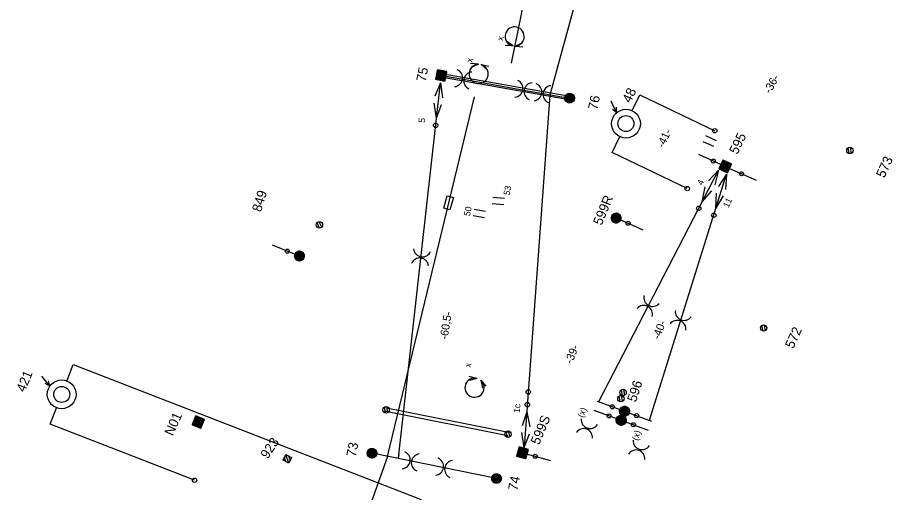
# Model space of a CAD drawing. Extents: x -595867 to -593796, y -1159595 to -1157495.
# Drawn here: x -594756.8 to -594620.1, y -1157925.4 to -1157851.2 of the extents above; entities that cross this region are included whole.
import ezdxf

# ---------------------------------------------------------------- set-up
doc = ezdxf.new("R2010")
doc.units = 0
for name, color, linetype in [('BVK_kanalizace_destova_nova', 7, 'Continuous'), ('BVK_kanalizace_jednotna_nova', 7, 'Continuous'), ('CD Telematika_novy', 7, 'Continuous')]:
    doc.layers.add(name, color=color, linetype=linetype)

# ---------------------------------------------------------------- blocks, each defined once
blk = doc.blocks.new('st_1t')
for points in [[(-0.0074, 0.0007), (0.0028, 0.0069), (0.0036, 0.0066), (-0.0075, -0.0002)], [(-0.0075, -0.0002), (0.0036, 0.0066), (0.0044, 0.006), (-0.0074, -0.001)], [(-0.0073, 0.0016), (0.0019, 0.0072), (0.0028, 0.0069), (-0.0074, 0.0007)], [(-0.0074, -0.001), (0.0044, 0.006), (0.0052, 0.0054), (-0.0072, -0.0019)], [(-0.0071, 0.0022), (0.0006, 0.0074), (0.0019, 0.0072), (-0.0073, 0.0016)], [(-0.0072, -0.0019), (0.0052, 0.0054), (0.0059, 0.0046), (-0.0069, -0.003)], [(-0.0069, 0.0029), (-0.0001, 0.0075), (0.0006, 0.0074), (-0.0071, 0.0022)], [(-0.0067, 0.0033), (-0.0015, 0.0073), (-0.0001, 0.0075), (-0.0069, 0.0029)], [(-0.0069, -0.003), (0.0059, 0.0046), (0.0067, 0.0034), (-0.0064, -0.0039)], [(-0.0063, 0.004), (-0.0022, 0.0071), (-0.0015, 0.0073), (-0.0067, 0.0033)], [(-0.0064, -0.0039), (0.0067, 0.0034), (0.0071, 0.0022), (-0.0057, -0.0049)], [(-0.0058, 0.0047), (-0.0032, 0.0068), (-0.0022, 0.0071), (-0.0063, 0.004)], [(-0.0053, 0.0053), (-0.0041, 0.0062), (-0.0032, 0.0068), (-0.0058, 0.0047)], [(-0.0057, -0.0049), (0.0071, 0.0022), (0.0074, 0.0011), (-0.0049, -0.0056)], [(-0.0049, -0.0056), (0.0074, 0.0011), (0.0075, -0.0004), (-0.004, -0.0063)], [(-0.004, -0.0063), (0.0075, -0.0004), (0.0073, -0.0017), (-0.0032, -0.0068)], [(-0.0032, -0.0068), (0.0073, -0.0017), (0.007, -0.0027), (-0.0021, -0.0072)], [(-0.0021, -0.0072), (0.007, -0.0027), (0.0065, -0.0037), (-0.0011, -0.0074)], [(-0.0011, -0.0074), (0.0065, -0.0037), (0.0059, -0.0046), (-0.0005, -0.0075)], [(-0.0005, -0.0075), (0.0059, -0.0046), (0.0054, -0.0052), (0.0004, -0.0075)], [(0.0004, -0.0075), (0.0054, -0.0052), (0.0045, -0.006), (0.0014, -0.0074)], [(0.0014, -0.0074), (0.0045, -0.006), (0.0038, -0.0064), (0.0025, -0.007)], [(0.0025, -0.007), (0.0038, -0.0064), (0.0029, -0.0069), (0.0029, -0.0069)]]:
    blk.add_lwpolyline(points, close=True)
blk.add_circle((0, 0), 0.0075)
blk = doc.blocks.new('st_tecka')
blk.add_circle((0, 0), 0.00314)
blk = doc.blocks.new('st1k_1t')
blk.add_line((0, 0), (0.0453, 0))
blk.add_blockref('st_1t', (0, 0))
at = {"rotation": 90}
blk.add_blockref('st_tecka', (0.0205, 0), dxfattribs=at)
blk = doc.blocks.new('st_bp')
for p, q in [((0.0075, 0.0075), (-0.0075, 0.0075)), ((-0.0075, 0.0075), (-0.0075, -0.0075)), ((-0.0075, -0.0075), (0.0075, 0.0075)), ((-0.0075, -0.0071), (0.0071, 0.0075)), ((-0.0075, -0.0067), (0.0067, 0.0075)), ((-0.0075, -0.0062), (0.0062, 0.0075)), ((-0.0075, -0.0058), (0.0058, 0.0075)), ((-0.0075, -0.0054), (0.0054, 0.0075)), ((-0.0075, -0.005), (0.005, 0.0075)), ((-0.0075, -0.0045), (0.0045, 0.0075)), ((-0.0075, -0.0041), (0.0041, 0.0075)), ((-0.0075, -0.0037), (0.0037, 0.0075)), ((-0.0075, -0.0033), (0.0033, 0.0075)), ((-0.0075, -0.0028), (0.0028, 0.0075)), ((-0.0075, -0.0024), (0.0024, 0.0075)), ((-0.0075, -0.002), (0.002, 0.0075)), ((-0.0075, -0.0016), (0.0016, 0.0075)), ((-0.0075, -0.0011), (0.0011, 0.0075)), ((-0.0075, -0.0007), (0.0007, 0.0075)), ((-0.0075, -0.0003), (0.0003, 0.0075)), ((-0.0075, 0.0001), (-0.0001, 0.0075)), ((-0.0075, 0.0006), (-0.0006, 0.0075)), ((-0.0075, 0.001), (-0.001, 0.0075)), ((-0.0075, 0.0014), (-0.0014, 0.0075)), ((-0.0075, 0.0018), (-0.0018, 0.0075)), ((-0.0075, 0.0023), (-0.0023, 0.0075)), ((-0.0075, 0.0027), (-0.0027, 0.0075)), ((-0.0075, 0.0031), (-0.0031, 0.0075)), ((-0.0075, 0.0035), (-0.0035, 0.0075)), ((-0.0075, 0.004), (-0.004, 0.0075)), ((-0.0075, 0.0044), (-0.0044, 0.0075)), ((-0.0075, 0.0048), (-0.0048, 0.0075)), ((-0.0075, 0.0052), (-0.0052, 0.0075)), ((-0.0075, 0.0057), (-0.0057, 0.0075)), ((-0.0075, 0.0061), (-0.0061, 0.0075)), ((-0.0075, 0.0065), (-0.0065, 0.0075)), ((-0.0075, 0.0069), (-0.0069, 0.0075)), ((-0.0075, 0.0073), (-0.0073, 0.0075)), ((-0.0071, -0.0075), (0.0075, 0.0071)), ((-0.0067, -0.0075), (0.0075, 0.0067)), ((-0.0062, -0.0075), (0.0075, 0.0062)), ((-0.0058, -0.0075), (0.0075, 0.0058)), ((-0.0054, -0.0075), (0.0075, 0.0054)), ((-0.005, -0.0075), (0.0075, 0.005)), ((-0.0045, -0.0075), (0.0075, 0.0045)), ((-0.0041, -0.0075), (0.0075, 0.0041)), ((-0.0037, -0.0075), (0.0075, 0.0037)), ((-0.0033, -0.0075), (0.0075, 0.0033)), ((-0.0028, -0.0075), (0.0075, 0.0028)), ((-0.0024, -0.0075), (0.0075, 0.0024)), ((-0.002, -0.0075), (0.0075, 0.002)), ((-0.0016, -0.0075), (0.0075, 0.0016)), ((-0.0011, -0.0075), (0.0075, 0.0011)), ((-0.0007, -0.0075), (0.0075, 0.0007)), ((-0.0003, -0.0075), (0.0075, 0.0003)), ((0.0075, -0.0075), (0.0075, 0.0075)), ((-0.0075, -0.0075), (0.0075, -0.0075)), ((0.0001, -0.0075), (0.0075, -0.0001)), ((0.0006, -0.0075), (0.0075, -0.0006)), ((0.001, -0.0075), (0.0075, -0.001)), ((0.0014, -0.0075), (0.0075, -0.0014)), ((0.0018, -0.0075), (0.0075, -0.0018)), ((0.0023, -0.0075), (0.0075, -0.0023)), ((0.0027, -0.0075), (0.0075, -0.0027)), ((0.0031, -0.0075), (0.0075, -0.0031)), ((0.0035, -0.0075), (0.0075, -0.0035)), ((0.004, -0.0075), (0.0075, -0.004)), ((0.0044, -0.0075), (0.0075, -0.0044)), ((0.0048, -0.0075), (0.0075, -0.0048)), ((0.0052, -0.0075), (0.0075, -0.0052)), ((0.0057, -0.0075), (0.0075, -0.0057)), ((0.0061, -0.0075), (0.0075, -0.0061)), ((0.0065, -0.0075), (0.0075, -0.0065)), ((0.0069, -0.0075), (0.0075, -0.0069)), ((0.0073, -0.0075), (0.0075, -0.0073))]:
    blk.add_line(p, q)
blk = doc.blocks.new('pol_sipk')
for q in [(0.0257, 0.0306), (0.0048, 0.0163), (0.0152, 0.0076)]:
    blk.add_line((0, 0), q)
blk = doc.blocks.new('odp_mzap')
for radius in [0.045, 0.025]:
    blk.add_circle((0, 0), radius)
blk.add_blockref('pol_sipk', (0.0179, 0.0413))
blk = doc.blocks.new('st_2t')
for points in [[(-0.0077, 0.0091), (0.0015, 0.0147), (0.0025, 0.0144), (-0.0078, 0.0082)], [(-0.0078, 0.0082), (0.0025, 0.0144), (0.0032, 0.014), (-0.0078, 0.0072)], [(-0.0078, 0.0072), (0.0032, 0.014), (0.004, 0.0135), (-0.0078, 0.0065)], [(-0.0075, 0.0097), (0.0002, 0.0149), (0.0015, 0.0147), (-0.0077, 0.0091)], [(-0.0073, 0.0104), (-0.0005, 0.015), (0.0002, 0.0149), (-0.0075, 0.0097)], [(-0.0071, 0.0108), (-0.0019, 0.0148), (-0.0005, 0.015), (-0.0073, 0.0104)], [(-0.0066, 0.0115), (-0.0026, 0.0146), (-0.0019, 0.0148), (-0.0071, 0.0108)], [(-0.0062, 0.0122), (-0.0035, 0.0142), (-0.0026, 0.0146), (-0.0066, 0.0115)], [(-0.0056, 0.0128), (-0.0045, 0.0137), (-0.0035, 0.0142), (-0.0062, 0.0122)], [(-0.0078, 0.0065), (0.004, 0.0135), (0.0048, 0.0129), (-0.0076, 0.0056)], [(-0.0076, 0.0056), (0.0048, 0.0129), (0.0055, 0.0121), (-0.0073, 0.0044)], [(-0.0073, 0.0044), (0.0055, 0.0121), (0.0063, 0.0109), (-0.0068, 0.0036)], [(-0.0068, 0.0036), (0.0063, 0.0109), (0.0067, 0.0097), (-0.006, 0.0026)], [(-0.006, 0.0026), (0.0067, 0.0097), (0.007, 0.0086), (-0.0052, 0.0018)], [(-0.0052, 0.0018), (0.007, 0.0086), (0.0071, 0.0071), (-0.0044, 0.0012)], [(-0.0044, 0.0012), (0.0071, 0.0071), (0.0069, 0.0057), (-0.0035, 0.0007)], [(-0.0035, 0.0007), (0.0069, 0.0057), (0.0066, 0.0047), (-0.0024, 0.0003)], [(-0.0024, 0.0003), (0.0066, 0.0047), (0.0061, 0.0038), (-0.0015, 0.0001)], [(-0.0015, 0.0001), (0.0061, 0.0038), (0.0055, 0.0029), (-0.0009, 0)], [(-0.0009, 0), (0.0055, 0.0029), (0.005, 0.0022), (0, 0)], [(0, 0), (0.005, 0.0022), (0.0041, 0.0015), (0.001, 0.0001)], [(0.001, 0.0001), (0.0041, 0.0015), (0.0035, 0.001), (0.0021, 0.0004)], [(0.0021, 0.0004), (0.0035, 0.001), (0.0026, 0.0006), (0.0026, 0.0005)], [(-0.0077, -0.0059), (0.0015, -0.0003), (0.0025, -0.0006), (-0.0078, -0.0068)], [(-0.0078, -0.0068), (0.0025, -0.0006), (0.0032, -0.001), (-0.0078, -0.0078)], [(-0.0078, -0.0078), (0.0032, -0.001), (0.004, -0.0015), (-0.0078, -0.0085)], [(-0.0078, -0.0085), (0.004, -0.0015), (0.0048, -0.0021), (-0.0076, -0.0094)], [(-0.0075, -0.0053), (0.0002, -0.0001), (0.0015, -0.0003), (-0.0077, -0.0059)], [(-0.0076, -0.0094), (0.0048, -0.0021), (0.0055, -0.0029), (-0.0073, -0.0106)], [(-0.0073, -0.0046), (-0.0005, 0), (0.0002, -0.0001), (-0.0075, -0.0053)], [(-0.0071, -0.0042), (-0.0019, -0.0002), (-0.0005, 0), (-0.0073, -0.0046)], [(-0.0073, -0.0106), (0.0055, -0.0029), (0.0063, -0.0041), (-0.0068, -0.0114)], [(-0.0066, -0.0035), (-0.0026, -0.0004), (-0.0019, -0.0002), (-0.0071, -0.0042)], [(-0.0068, -0.0114), (0.0063, -0.0041), (0.0067, -0.0053), (-0.006, -0.0124)], [(-0.0062, -0.0028), (-0.0035, -0.0008), (-0.0026, -0.0004), (-0.0066, -0.0035)], [(-0.0056, -0.0022), (-0.0045, -0.0013), (-0.0035, -0.0008), (-0.0062, -0.0028)], [(-0.006, -0.0124), (0.0067, -0.0053), (0.007, -0.0064), (-0.0052, -0.0132)], [(-0.0052, -0.0132), (0.007, -0.0064), (0.0071, -0.0079), (-0.0044, -0.0138)], [(-0.0044, -0.0138), (0.0071, -0.0079), (0.0069, -0.0093), (-0.0035, -0.0143)], [(-0.0035, -0.0143), (0.0069, -0.0093), (0.0066, -0.0103), (-0.0024, -0.0147)], [(-0.0024, -0.0147), (0.0066, -0.0103), (0.0061, -0.0112), (-0.0015, -0.0149)], [(-0.0015, -0.0149), (0.0061, -0.0112), (0.0055, -0.0121), (-0.0009, -0.015)], [(-0.0009, -0.015), (0.0055, -0.0121), (0.005, -0.0128), (0, -0.015)], [(0, -0.015), (0.005, -0.0128), (0.0041, -0.0135), (0.001, -0.0149)], [(0.001, -0.0149), (0.0041, -0.0135), (0.0035, -0.014), (0.0021, -0.0146)], [(0.0021, -0.0146), (0.0035, -0.014), (0.0026, -0.0144), (0.0026, -0.0145)]]:
    blk.add_lwpolyline(points, close=True)
for centre in [(-0.0004, 0.0075), (-0.0004, -0.0075)]:
    blk.add_circle(centre, 0.0075)
blk = doc.blocks.new('st2k_2t')
for p, q in [((-0.0004, 0.0075), (0.0449, 0.0075)), ((-0.0004, -0.0075), (0.0449, -0.0075))]:
    blk.add_line(p, q)
blk.add_blockref('st_2t', (0, 0))
at = {"rotation": 90}
for p in [(0.0202, 0.0075), (0.0202, -0.0075)]:
    blk.add_blockref('st_tecka', p, dxfattribs=at)
blk = doc.blocks.new('st1k_bp')
blk.add_line((0, 0), (0.0453, 0))
blk.add_blockref('st_bp', (0, 0))
at = {"rotation": 90}
blk.add_blockref('st_tecka', (0.0205, 0), dxfattribs=at)
blk = doc.blocks.new('pol_delic')
for p, q in [((-0.005, -0.009), (-0.005, 0.009)), ((0.005, -0.009), (0.005, 0.009))]:
    blk.add_line(p, q)
blk = doc.blocks.new('st1k_konzola')
blk.add_line((0, 0), (0.0453, 0))
at = {"rotation": 90}
blk.add_blockref('st_tecka', (0.0205, 0), dxfattribs=at)
blk = doc.blocks.new('pol_sipka2')
for q in [(0.0123, 0.003), (0.0118, -0.0034)]:
    blk.add_line((0, 0), q)
blk = doc.blocks.new('kotv_tecka')
blk.add_circle((0, 0), 0.00345)
blk = doc.blocks.new('kotv_polok')
for p, q in [((-0.0558, 0), (-0.0328, 0.0065)), ((-0.0558, 0), (-0.0336, -0.0056)), ((0, 0), (-0.023, -0.0056))]:
    blk.add_line(p, q)
blk.add_lwpolyline([(0, 0), (-0.0221, 0.0064)])
blk.add_blockref('kotv_tecka', (-0.067, 0))
blk = doc.blocks.new('pol_izol')
for centre, start, end in [((-0.0148, 0), 284.4047, 75.5953), ((0.0148, 0), 104.4047, 255.5953)]:
    blk.add_arc(centre, 0.0138, start, end)
blk = doc.blocks.new('kotv_poh')
for p, q in [((-0.0558, 0), (-0.0328, 0.0065)), ((-0.0558, 0), (-0.0336, -0.0056)), ((0, 0), (-0.023, -0.0056))]:
    blk.add_line(p, q)
blk.add_lwpolyline([(0, 0), (-0.0221, 0.0064)])
for p in [(-0.087, 0), (-0.0671, 0)]:
    blk.add_blockref('kotv_tecka', p)
blk = doc.blocks.new('pol_sjsp')
for p, q in [((-0.01, 0.005), (0.01, 0.005)), ((-0.01, -0.005), (-0.01, 0.005)), ((0.01, 0.005), (0.01, -0.005)), ((0.01, -0.005), (-0.01, -0.005))]:
    blk.add_line(p, q)

msp = doc.modelspace()

# ---------------------------------------------------------------- linework, layer by layer
at = {"layer": 'BVK_kanalizace_destova_nova'}
for p, q in [((-594690.6, -1157860.27), (-594687.19, -1157860.87)), ((-594677.69, -1157862.56), (-594670.54, -1157863.82)), ((-594660.78, -1157865.77), (-594659.58, -1157863.29)), ((-594659.58, -1157863.29), (-594647.85, -1157868.93)), ((-594663.92, -1157872.3), (-594662.72, -1157869.82)), ((-594652.17, -1157877.95), (-594663.92, -1157872.3)), ((-594666.03, -1157911.29), (-594647.3, -1157875.07)), ((-594658.06, -1157914.12), (-594646.03, -1157875.72)), ((-594751.66, -1157914.75), (-594750.67, -1157912.19)), ((-594729.11, -1157923.5), (-594751.66, -1157914.75)), ((-594697.24, -1157919.98), (-594697.14, -1157919.49))]:
    msp.add_line(p, q, dxfattribs=at)
at = {"layer": 'BVK_kanalizace_jednotna_nova'}
for p, q in [((-594690.83, -1157860.71), (-594691.07, -1157860.09)), ((-594690.35, -1157860.93), (-594690.85, -1157859.61)), ((-594690.13, -1157860.45), (-594690.37, -1157859.82)), ((-594670.67, -1157864.29), (-594670.83, -1157863.39)), ((-594670.3, -1157864.24), (-594670.46, -1157863.32)), ((-594626.89, -1157872.47), (-594627.05, -1157871.57)), ((-594626.52, -1157872.41), (-594626.68, -1157871.5)), ((-594645.59, -1157874.25), (-594646.91, -1157874.74)), ((-594646.07, -1157874.02), (-594646.69, -1157874.26)), ((-594645.81, -1157874.73), (-594646.43, -1157874.96)), ((-594663.28, -1157883.04), (-594663.64, -1157882.2)), ((-594662.93, -1157882.89), (-594663.3, -1157882.04)), ((-594709.61, -1157884.11), (-594709.97, -1157883.28)), ((-594709.26, -1157883.97), (-594709.63, -1157883.12)), ((-594640.35, -1157900.2), (-594640.51, -1157899.3)), ((-594639.98, -1157900.14), (-594640.14, -1157899.23)), ((-594662.31, -1157910.28), (-594662.47, -1157909.38)), ((-594661.94, -1157910.23), (-594662.1, -1157909.31)), ((-594662.65, -1157911.24), (-594662.81, -1157910.34)), ((-594662.28, -1157911.19), (-594662.44, -1157910.27)), ((-594699.31, -1157912.99), (-594699.47, -1157912.09)), ((-594698.94, -1157912.94), (-594699.1, -1157912.02)), ((-594728.27, -1157915.06), (-594728.77, -1157913.74)), ((-594728.75, -1157914.84), (-594728.99, -1157914.23)), ((-594728.05, -1157914.58), (-594728.29, -1157913.95)), ((-594680.27, -1157916.78), (-594680.43, -1157915.88)), ((-594679.9, -1157916.73), (-594680.06, -1157915.81)), ((-594678.11, -1157919.62), (-594678.37, -1157919.01)), ((-594677.61, -1157919.81), (-594678.18, -1157918.52)), ((-594677.42, -1157919.32), (-594677.69, -1157918.71)), ((-594714.88, -1157920.59), (-594715.08, -1157919.97)), ((-594714.4, -1157920.83), (-594714.85, -1157919.49)), ((-594714.16, -1157920.36), (-594714.38, -1157919.73))]:
    msp.add_line(p, q, dxfattribs=at)
for points in [[(-594691.26, -1157860.52), (-594690.85, -1157859.61), (-594689.94, -1157860.02), (-594690.35, -1157860.93)], [(-594646, -1157875.15), (-594646.91, -1157874.73), (-594646.5, -1157873.83), (-594645.59, -1157874.24)], [(-594729.18, -1157914.65), (-594728.77, -1157913.74), (-594727.86, -1157914.14), (-594728.26, -1157915.06)], [(-594678.54, -1157919.45), (-594678.18, -1157918.51), (-594677.24, -1157918.88), (-594677.61, -1157919.81)], [(-594715.29, -1157920.38), (-594714.85, -1157919.49), (-594713.95, -1157919.94), (-594714.4, -1157920.83)]]:
    msp.add_lwpolyline(points, close=True, dxfattribs=at)
for points in [[(-594691.26, -1157860.52), (-594690.85, -1157859.61), (-594689.94, -1157860.02), (-594690.35, -1157860.93), (-594691.26, -1157860.52)], [(-594670.6, -1157864.06), (-594690.64, -1157860.52)], [(-594670.52, -1157863.56), (-594690.56, -1157860.02)], [(-594646, -1157875.15), (-594646.91, -1157874.73), (-594646.5, -1157873.83), (-594645.59, -1157874.24), (-594646, -1157875.15)], [(-594680.11, -1157916.05), (-594699.15, -1157912.26)], [(-594729.18, -1157914.65), (-594728.77, -1157913.74), (-594727.86, -1157914.14), (-594728.26, -1157915.06), (-594729.18, -1157914.65)], [(-594680.21, -1157916.54), (-594699.25, -1157912.76)], [(-594678.54, -1157919.45), (-594678.18, -1157918.51), (-594677.24, -1157918.88), (-594677.61, -1157919.81), (-594678.54, -1157919.45)], [(-594715.29, -1157920.38), (-594714.85, -1157919.49), (-594713.95, -1157919.94), (-594714.4, -1157920.83), (-594715.29, -1157920.38)]]:
    msp.add_lwpolyline(points, dxfattribs=at)
for centre in [(-594670.56, -1157863.81), (-594670.56, -1157863.81), (-594626.78, -1157871.99), (-594626.78, -1157871.99), (-594663.28, -1157882.54), (-594663.28, -1157882.54), (-594709.61, -1157883.62), (-594709.61, -1157883.62), (-594640.24, -1157899.72), (-594640.24, -1157899.72), (-594662.2, -1157909.8), (-594662.2, -1157909.8), (-594662.54, -1157910.76), (-594662.54, -1157910.76), (-594699.2, -1157912.51), (-594699.2, -1157912.51), (-594680.16, -1157916.3), (-594680.16, -1157916.3)]:
    msp.add_circle(centre, 0.5, dxfattribs=at)
at = {"layer": 'CD Telematika_novy'}
for p, q in [((-594679.63, -1157858.37), (-594664.36, -1157782.7)), ((-594656.86, -1157801.53), (-594673.64, -1157863.37)), ((-594697.26, -1157919.98), (-594690.71, -1157861.41)), ((-594687.13, -1157860.88), (-594677.72, -1157862.55)), ((-594673.64, -1157863.37), (-594677.63, -1157918.39)), ((-594699, -1157919.8), (-594685.41, -1157863.59)), ((-594749.04, -1157908), (-594748.05, -1157905.43)), ((-594748.05, -1157905.43), (-594693.7, -1157926.5)), ((-594681.96, -1157923.23), (-594701.4, -1157919.28)), ((-594699, -1157919.8), (-594712.93, -1157959.06))]:
    msp.add_line(p, q, dxfattribs=at)
for centre, start, end in [((-594679.14, -1157854.19), 273.3905, 261.6172), ((-594684.74, -1157860.03), 91.8963, 75.2688), ((-594685.39, -1157909.04), 75.7193, 50.1842)]:
    msp.add_arc(centre, 1.5, start, end, dxfattribs=at)

# ---------------------------------------------------------------- block references
at = {"layer": 'BVK_kanalizace_destova_nova'}
for name, p, xscale, yscale, rotation in [('st_bp', (-594690.6, -1157860.27), 100, 100, -11.483148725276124), ('pol_izol', (-594687.17, -1157860.88), 100, 99.99999999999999, -9.052350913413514), ('kotv_polok', (-594690.71, -1157861.41), 100, 100.00000000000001, 83.61431718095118), ('pol_izol', (-594677.75, -1157862.55), 100.00000000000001, 100, -9.51887236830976), ('pol_izol', (-594674.79, -1157863.05), 100, 100.00000000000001, -7.474819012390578), ('st_1t', (-594670.54, -1157863.82), 100.00000000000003, 99.99999999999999, 79.51685128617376), ('odp_mzap', (-594661.75, -1157867.8), 50, 50, 64.3290814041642), ('kotv_tecka', (-594647.88, -1157868.91), 100, 100, 65.3290814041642), ('pol_delic', (-594648.65, -1157870.56), 99.99999999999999, 100, 65.41114768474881), ('st1k_bp', (-594646.25, -1157874.49), 100, 100, 155.67690080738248), ('kotv_polok', (-594647.3, -1157875.07), 100, 100, 62.64779636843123), ('kotv_polok', (-594646.03, -1157875.72), 100, 100, 72.59888296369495), ('st1k_konzola', (-594645.57, -1157874.8), 100, 100.00000000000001, -24.133090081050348), ('kotv_tecka', (-594652.17, -1157877.95), 100, 100, 65.3290814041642), ('st1k_1t', (-594663.28, -1157882.54), 99.99999999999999, 100.00000000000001, -23.766025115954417), ('st1k_1t', (-594712.73, -1157888.48), 99.99999999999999, 100.00000000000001, 158.3119260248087), ('pol_izol', (-594658.29, -1157896.28), 100, 100, 61.94632937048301), ('pol_izol', (-594653.21, -1157898.53), 100, 100, 68.42159345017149), ('odp_mzap', (-594749.85, -1157910.09), 50, 50, 78.51685128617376), ('st2k_2t', (-594662.23, -1157913.43), 100, 100, 159.99107759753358), ('st2k_2t', (-594662.23, -1157913.43), 100, 100, -19.93210964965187), ('st_bp', (-594728.52, -1157914.4), 100, 100, -22.110286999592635), ('pol_izol', (-594667.85, -1157915.43), 100.00000000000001, 100, 70.17134428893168), ('pol_izol', (-594659.71, -1157918.74), 100, 100.00000000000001, 71.98815267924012), ('kotv_tecka', (-594729.11, -1157923.5), 99.99999999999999, 100.00000000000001, 69.80947331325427)]:
    msp.add_blockref(name, p, dxfattribs=dict(at, xscale=xscale, yscale=yscale, rotation=rotation))
at = {"layer": 'CD Telematika_novy'}
for name, p, xscale, yscale, rotation in [('pol_sipka2', (-594679.36, -1157855.67), 100, -100.00000000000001, 159.6570021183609), ('pol_sipka2', (-594679.05, -1157855.68), 100.00000000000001, 99.99999999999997, 10.37206689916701), ('pol_sipka2', (-594684.79, -1157858.53), 100, 100.00000000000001, -170.23227646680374), ('pol_sipka2', (-594684.36, -1157858.58), 100, -100, -28.119432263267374), ('pol_sjsp', (-594689.45, -1157880.16), 100, 100.00000000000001, 74.1530393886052), ('pol_delic', (-594681.68, -1157879.91), 100, 99.99999999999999, 83.83383553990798), ('pol_delic', (-594684.63, -1157881.88), 100, 100.00000000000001, 80.33356454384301), ('pol_izol', (-594693.74, -1157888.69), 100, 100, 81.71537104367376), ('pol_sipka2', (-594685.02, -1157907.59), 100, 99.99999999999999, -178.0887957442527), ('pol_sipka2', (-594684.43, -1157907.89), 100, -99.99999999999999, -64.30640330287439), ('kotv_poh', (-594677.63, -1157918.39), 100, 100.00000000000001, -94.14582899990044), ('st_1t', (-594701.4, -1157919.28), 100.00000000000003, 99.99999999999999, 79.51685128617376), ('pol_izol', (-594695.35, -1157920.55), 100, 100, -8.635281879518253), ('st1k_bp', (-594677.89, -1157919.2), 100.00000000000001, 100, -15.761833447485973), ('pol_izol', (-594690.15, -1157921.56), 100.00000000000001, 99.99999999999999, -8.861996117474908), ('st_1t', (-594681.96, -1157923.23), 100.00000000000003, 99.99999999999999, 79.51685128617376)]:
    msp.add_blockref(name, p, dxfattribs=dict(at, xscale=xscale, yscale=yscale, rotation=rotation))

# ---------------------------------------------------------------- texts
at = {"layer": 'BVK_kanalizace_destova_nova'}
for s, height, rotation, p in [('75', 1.5, 79.0205, (-594693.03, -1157861.34)), ('-36-', 1.25, 61.1477, (-594639.21, -1157863.21)), ('48', 1.5, 64.2787, (-594661.05, -1157864.69)), ('76', 1.5, 79.0205, (-594666.21, -1157865.74)), ('5', 1, 85.5479, (-594693.14, -1157867.69)), ('-41-', 1.25, 64.4451, (-594655.88, -1157871.68)), ('595', 1.5, 64.2787, (-594644.36, -1157872.71)), ('4', 1, 65.2067, (-594649.82, -1157877.51)), ('599R', 1.5, 67.4643, (-594665.56, -1157883.8)), ('11', 1, 65.2067, (-594645.74, -1157881.03)), ('-40-', 1.25, 68.8386, (-594656.52, -1157901.61)), ('-39-', 1.25, 68.3562, (-594670.18, -1157905.42)), ('421', 1.5, 67.5907, (-594755.63, -1157909.85)), ('596', 1.5, 71.7291, (-594660.19, -1157911.39)), ('(x)', 1, 69.5419, (-594668.39, -1157913.81)), ('N01', 1.5, 65.9992, (-594732.51, -1157916.68)), ('(x)', 1, 69.5419, (-594659.92, -1157917.39))]:
    msp.add_text(s, height=height, rotation=rotation, dxfattribs=at).set_placement(p)
at = {"layer": 'BVK_kanalizace_jednotna_nova'}
for s, rotation, p in [('573', 65.5984, (-594621.4, -1157876.39)), ('849', 72.8965, (-594718.75, -1157881.7)), ('572', 65.5984, (-594635.62, -1157903.04)), ('923', 56, (-594717.7, -1157920.27))]:
    msp.add_text(s, height=1.5, rotation=rotation, dxfattribs=at).set_placement(p)
at = {"layer": 'CD Telematika_novy'}
for s, height, rotation, p in [('x', 1, 77.795, (-594680.95, -1157854.91)), ('x', 1, 77.795, (-594685.74, -1157858.31)), ('53', 1, 77.795, (-594679.93, -1157879.06)), ('50', 1, 77.795, (-594686.12, -1157882.32)), ('-60,5-', 1.25, 80.8777, (-594689.61, -1157901.57)), ('x', 1, 77.795, (-594686, -1157905.93)), ('1c', 1, 85.5479, (-594678.32, -1157913.01)), ('599S', 1.5, 67.4643, (-594675.31, -1157918.07)), ('73', 1.5, 79.0205, (-594703.95, -1157919.93)), ('74', 1.5, 79.0205, (-594678.7, -1157925.2))]:
    msp.add_text(s, height=height, rotation=rotation, dxfattribs=at).set_placement(p)

doc.saveas('drawing.dxf')
